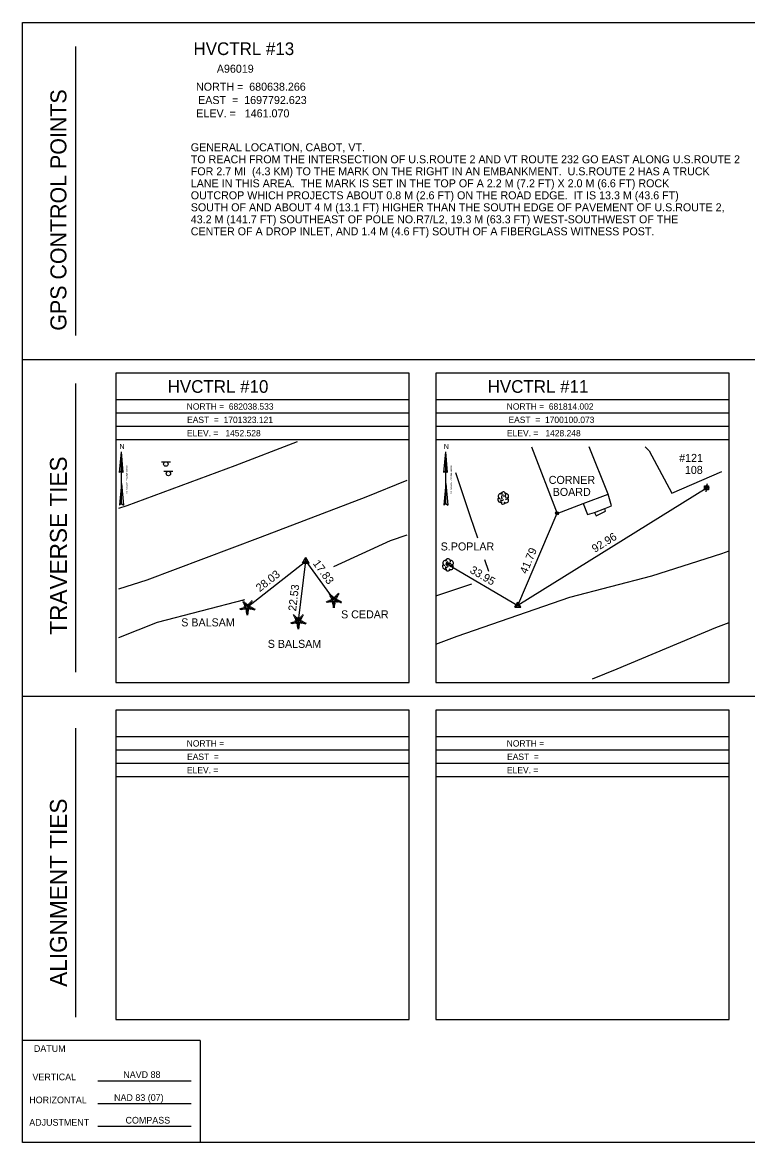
# Model space of a CAD drawing. Extents: x 1702290 to 1703620, y 686233 to 686653.
# Drawn here: x 1702980.5 to 1703252.4, y 686232.9 to 686652.9 of the extents above; entities that cross this region are included whole.
import ezdxf

# ---------------------------------------------------------------- set-up
doc = ezdxf.new("R2010")
doc.units = 0
for name, color, linetype in [('C_C', 7, 'Continuous'), ('CBP', 7, 'Continuous'), ('CPSM', 7, 'Continuous'), ('Default', 7, 'Continuous'), ('L_C', 7, 'Continuous'), ('LABL', 7, 'Continuous'), ('LAWA', 7, 'Continuous'), ('LBC', 7, 'Continuous'), ('LBF', 7, 'Continuous'), ('LTC', 7, 'Continuous'), ('LTD', 7, 'Continuous'), ('NBL1', 7, 'Continuous'), ('NBL2', 7, 'Continuous'), ('NNA_P', 7, 'Continuous'), ('PET', 7, 'Continuous'), ('SSGN', 7, 'Continuous'), ('U_C', 7, 'Continuous'), ('UP', 7, 'Continuous')]:
    doc.layers.add(name, color=color, linetype=linetype)

msp = doc.modelspace()

# ---------------------------------------------------------------- linework, layer by layer
at = {"layer": 'CBP'}
for centre, radius in [((1703237.33, 686478.43), 0.562), ((1703237.33, 686478.43), 0.075), ((1703181.02, 686468.85), 0.562), ((1703181.02, 686468.85), 0.075), ((1703139.95, 686449.77), 0.562), ((1703139.95, 686449.77), 0.075), ((1703097.25, 686436.43), 0.625), ((1703097.25, 686436.43), 0.0833), ((1703064.72, 686433.61), 0.625), ((1703064.72, 686433.61), 0.0833), ((1703084.06, 686428.51), 0.625), ((1703084.06, 686428.51), 0.0833)]:
    msp.add_circle(centre, radius, dxfattribs=at)
at = {"layer": 'CPSM'}
for p, q in [((1703085.55, 686450.16), (1703086.8, 686452.33)), ((1703088.05, 686450.16), (1703086.8, 686452.33)), ((1703086.8, 686450.88), (1703086.8, 686452.33)), ((1703085.55, 686450.16), (1703086.8, 686450.88)), ((1703085.55, 686450.16), (1703088.05, 686450.16)), ((1703086.8, 686450.88), (1703086.8, 686450.88)), ((1703086.8, 686450.88), (1703088.05, 686450.16)), ((1703165.14, 686433.6), (1703166.27, 686435.55)), ((1703167.39, 686433.6), (1703166.27, 686435.55)), ((1703166.27, 686434.25), (1703166.27, 686435.55)), ((1703165.14, 686433.6), (1703166.27, 686434.25)), ((1703165.14, 686433.6), (1703167.39, 686433.6)), ((1703166.27, 686434.25), (1703166.27, 686434.25)), ((1703166.27, 686434.25), (1703167.39, 686433.6))]:
    msp.add_line(p, q, dxfattribs=at)
at = {"layer": 'Default'}
for p, q in [((1703237.33, 686478.43), (1703166.27, 686434.25)), ((1703166.27, 686434.25), (1703181.02, 686468.85)), ((1703064.72, 686433.61), (1703086.8, 686450.88)), ((1703084.06, 686428.51), (1703086.8, 686450.88)), ((1703086.8, 686450.88), (1703097.25, 686436.43)), ((1703139.95, 686449.77), (1703166.27, 686434.25))]:
    msp.add_line(p, q, dxfattribs=at)
at = {"layer": 'LABL'}
for points in [[(1703151.22, 686459.51), (1703148.57, 686467.53), (1703143.01, 686483.97)], [(1703155.36, 686446.98), (1703153.91, 686451.39)], [(1703135.49, 686437.93), (1703148.99, 686442.39)]]:
    msp.add_lwpolyline(points, dxfattribs=at)
at = {"layer": 'LAWA'}
for points in [[(1703214.08, 686493.75), (1703215.47, 686492.29), (1703223.99, 686476.44), (1703242.82, 686484.48)], [(1703097.31, 686448.93), (1703118.5, 686458.68), (1703124.74, 686460.76)], [(1703016.69, 686422.33), (1703031.19, 686428.02), (1703063.96, 686436.53)]]:
    msp.add_lwpolyline(points, dxfattribs=at)
at = {"layer": 'LBC'}
msp.add_lwpolyline([(1703171.37, 686493.75), (1703180.98, 686468.78), (1703190.8, 686472.47), (1703200.1, 686476.07), (1703193.08, 686493.75)], dxfattribs=at)
at = {"layer": 'LBF'}
for points in [[(1703190.8, 686472.47), (1703192.35, 686468.33), (1703194.98, 686469.18), (1703198.87, 686470.66), (1703201.43, 686471.59), (1703200.1, 686476.07)], [(1703194.98, 686469.18), (1703195.61, 686467.89), (1703199.09, 686469.69), (1703198.87, 686470.66)]]:
    msp.add_lwpolyline(points, dxfattribs=at)
at = {"layer": 'LTC'}
for p, q in [((1703062.98, 686435.85), (1703063.33, 686436.11)), ((1703063.19, 686435.38), (1703063.72, 686435.77)), ((1703063.4, 686434.92), (1703064.1, 686435.43)), ((1703066, 686435.74), (1703066.55, 686435.34)), ((1703066.38, 686436.09), (1703066.79, 686435.78)), ((1703094.45, 686435.89), (1703094.6, 686435.42)), ((1703094.9, 686436.11), (1703095.11, 686435.46)), ((1703095.36, 686436.33), (1703095.63, 686435.49)), ((1703095.41, 686438.61), (1703095.77, 686438.87)), ((1703095.62, 686438.15), (1703096.15, 686438.53)), ((1703095.81, 686436.54), (1703096.14, 686435.52)), ((1703095.83, 686437.68), (1703096.54, 686438.19)), ((1703096.04, 686437.22), (1703096.92, 686437.85)), ((1703096.27, 686436.76), (1703097.28, 686437.5)), ((1703096.27, 686436.76), (1703096.66, 686435.57)), ((1703097.89, 686435.57), (1703096.66, 686435.57)), ((1703097.28, 686437.5), (1703098.28, 686436.77)), ((1703097.7, 686437.81), (1703098.51, 686437.22)), ((1703098.28, 686436.77), (1703097.89, 686435.57)), ((1703098.07, 686438.16), (1703098.75, 686437.66)), ((1703098.71, 686436.5), (1703098.38, 686435.46)), ((1703098.44, 686438.51), (1703098.99, 686438.11)), ((1703098.81, 686438.85), (1703099.23, 686438.55)), ((1703099.16, 686436.25), (1703098.87, 686435.37)), ((1703099.6, 686436), (1703099.37, 686435.27)), ((1703100.05, 686435.75), (1703099.86, 686435.18)), ((1703062.01, 686433.13), (1703062.16, 686432.66)), ((1703062.46, 686433.34), (1703062.68, 686432.69)), ((1703062.92, 686433.56), (1703063.19, 686432.72)), ((1703063.38, 686433.78), (1703063.71, 686432.76)), ((1703063.61, 686434.45), (1703064.48, 686435.09)), ((1703063.83, 686434), (1703064.84, 686434.73)), ((1703063.83, 686434), (1703064.22, 686432.8)), ((1703065.45, 686432.8), (1703064.22, 686432.8)), ((1703065.41, 686432.3), (1703064.26, 686432.3)), ((1703065.33, 686431.8), (1703064.34, 686431.8)), ((1703065.24, 686431.3), (1703064.41, 686431.3)), ((1703064.84, 686434.73), (1703065.84, 686434.01)), ((1703065.26, 686435.04), (1703066.07, 686434.45)), ((1703065.84, 686434.01), (1703065.45, 686432.8)), ((1703065.63, 686435.39), (1703066.31, 686434.9)), ((1703066.28, 686433.73), (1703065.94, 686432.69)), ((1703066.72, 686433.48), (1703066.43, 686432.6)), ((1703067.17, 686433.23), (1703066.93, 686432.5)), ((1703067.61, 686432.98), (1703067.42, 686432.41)), ((1703097.85, 686435.07), (1703096.7, 686435.07)), ((1703097.76, 686434.57), (1703096.78, 686434.57)), ((1703097.68, 686434.07), (1703096.85, 686434.07)), ((1703097.6, 686433.57), (1703096.92, 686433.57)), ((1703065.16, 686430.8), (1703064.48, 686430.8)), ((1703081.12, 686427.87), (1703081.28, 686427.41)), ((1703081.58, 686428.09), (1703081.79, 686427.44)), ((1703082.03, 686428.31), (1703082.31, 686427.47)), ((1703082.09, 686430.6), (1703082.45, 686430.85)), ((1703082.3, 686430.13), (1703082.83, 686430.51)), ((1703082.49, 686428.52), (1703082.82, 686427.51)), ((1703082.51, 686429.66), (1703083.21, 686430.18)), ((1703082.72, 686429.2), (1703083.6, 686429.84)), ((1703082.94, 686428.74), (1703083.96, 686429.48)), ((1703082.94, 686428.74), (1703083.33, 686427.55)), ((1703084.56, 686427.55), (1703083.33, 686427.55)), ((1703084.52, 686427.05), (1703083.38, 686427.05)), ((1703083.96, 686429.48), (1703084.95, 686428.75)), ((1703084.38, 686429.79), (1703085.19, 686429.2)), ((1703084.95, 686428.75), (1703084.56, 686427.55)), ((1703084.75, 686430.14), (1703085.43, 686429.65)), ((1703085.39, 686428.48), (1703085.05, 686427.44)), ((1703085.12, 686430.49), (1703085.67, 686430.09)), ((1703085.49, 686430.84), (1703085.91, 686430.53)), ((1703085.83, 686428.23), (1703085.55, 686427.35)), ((1703086.28, 686427.98), (1703086.04, 686427.25)), ((1703086.72, 686427.73), (1703086.54, 686427.16)), ((1703084.44, 686426.55), (1703083.45, 686426.55)), ((1703084.36, 686426.05), (1703083.52, 686426.05)), ((1703084.27, 686425.55), (1703083.6, 686425.55))]:
    msp.add_line(p, q, dxfattribs=at)
at = {"layer": 'LTD'}
for p, q in [((1703160.79, 686474.63), (1703160.79, 686474.63)), ((1703160.79, 686474.63), (1703160.79, 686474.63)), ((1703140.07, 686449.58), (1703140.07, 686449.58)), ((1703140.07, 686449.58), (1703140.07, 686449.58))]:
    msp.add_line(p, q, dxfattribs=at)
for centre in [(1703160.83, 686475.92), (1703140.11, 686450.87)]:
    msp.add_arc(centre, 0.942, 335.5272, 180.9563, dxfattribs=at)
for centre, major_axis, ratio, start_param, end_param in [((1703159.82, 686473.99), (0.525, -0.937), 0.959034, 3.141593, 6.283185), ((1703160.08, 686475.23), (1.09, -0.46), 0.895232, 1.570796, 4.712389), ((1703160.79, 686473.28), (0.238, 0.955), 0.942809, 1.570796, 4.712389), ((1703160.38, 686473.95), (-0.562, -0.075), 0.423636, 0, 3.141593), ((1703160.61, 686475.04), (-0.187, -0.713), 0.645439, 3.141593, 6.283185), ((1703161.24, 686474.48), (-0.45, 0.6), 0.989748, 3.141593, 6.283185), ((1703161.69, 686473.88), (-0.981, 0.713), 0.841452, 1.570796, 4.712389), ((1703161.73, 686475.15), (-1.03, -0.43), 0.949671, 1.570796, 4.712389), ((1703139.09, 686448.94), (0.525, -0.937), 0.959034, 3.141593, 6.283185), ((1703139.35, 686450.18), (1.09, -0.46), 0.895232, 1.570796, 4.712389), ((1703140.07, 686448.23), (0.238, 0.955), 0.942809, 1.570796, 4.712389), ((1703139.65, 686448.9), (-0.562, -0.075), 0.423636, 0, 3.141593), ((1703139.88, 686449.99), (-0.187, -0.713), 0.645439, 3.141593, 6.283185), ((1703140.52, 686449.43), (-0.45, 0.6), 0.989748, 3.141593, 6.283185), ((1703140.97, 686448.83), (-0.981, 0.713), 0.841452, 1.570796, 4.712389), ((1703141, 686450.1), (-1.03, -0.43), 0.949671, 1.570796, 4.712389)]:
    msp.add_ellipse(centre, major_axis=major_axis, ratio=ratio, start_param=start_param, end_param=end_param, dxfattribs=at)
at = {"layer": 'NBL1'}
for p, q in [((1703000.49, 686535.56), (1703000.49, 686643.9)), ((1702980.49, 686526.56), (1703620.49, 686526.56)), ((1703000.49, 686409.23), (1703000.49, 686517.56)), ((1702980.49, 686400.23), (1703620.49, 686400.23)), ((1703000.49, 686279.9), (1703000.49, 686388.23)), ((1703125.49, 686385.06), (1703015.49, 686385.06)), ((1703245.49, 686385.06), (1703135.49, 686385.06)), ((1703125.49, 686380.06), (1703015.49, 686380.06)), ((1703245.49, 686380.06), (1703135.49, 686380.06)), ((1703125.49, 686375.06), (1703015.49, 686375.06)), ((1703245.49, 686375.06), (1703135.49, 686375.06)), ((1703125.49, 686370.06), (1703015.49, 686370.06)), ((1703245.49, 686370.06), (1703135.49, 686370.06))]:
    msp.add_line(p, q, dxfattribs=at)
for points in [[(1703620.49, 686232.9), (1702980.49, 686232.9), (1702980.49, 686652.9), (1703620.49, 686652.9)], [(1703015.49, 686279.06), (1703125.49, 686279.06), (1703125.49, 686395.06), (1703015.49, 686395.06)], [(1703135.49, 686279.06), (1703245.49, 686279.06), (1703245.49, 686395.06), (1703135.49, 686395.06)]]:
    msp.add_lwpolyline(points, close=True, dxfattribs=at)
at = {"layer": 'NBL2'}
for p, q in [((1703125.49, 686511.38), (1703015.49, 686511.38)), ((1703245.49, 686511.38), (1703135.49, 686511.38)), ((1703125.49, 686506.38), (1703015.49, 686506.38)), ((1703245.49, 686506.38), (1703135.49, 686506.38)), ((1703125.49, 686501.38), (1703015.49, 686501.38)), ((1703245.49, 686501.38), (1703135.49, 686501.38)), ((1703125.49, 686496.38), (1703015.49, 686496.38)), ((1703245.49, 686496.38), (1703135.49, 686496.38)), ((1703047.16, 686271.15), (1702980.49, 686271.15)), ((1703047.16, 686271.15), (1703047.16, 686232.9)), ((1703047.16, 686271.15), (1703047.16, 686232.9)), ((1703008.73, 686256.09), (1703043.73, 686256.09)), ((1703008.73, 686247.5), (1703043.73, 686247.5)), ((1703008.73, 686239.06), (1703043.73, 686239.06))]:
    msp.add_line(p, q, dxfattribs=at)
for points in [[(1703015.49, 686405.38), (1703125.49, 686405.38), (1703125.49, 686521.38), (1703015.49, 686521.38)], [(1703135.49, 686405.38), (1703245.49, 686405.38), (1703245.49, 686521.38), (1703135.49, 686521.38)]]:
    msp.add_lwpolyline(points, close=True, dxfattribs=at)
at = {"layer": 'NNA_P'}
for p, q in [((1703016.95, 686484.1), (1703017.64, 686491.89)), ((1703017.64, 686472.52), (1703017.64, 686491.89)), ((1703018.34, 686484.1), (1703017.64, 686491.89)), ((1703138.56, 686484.1), (1703139.25, 686491.89)), ((1703139.26, 686472.52), (1703139.25, 686491.89)), ((1703139.95, 686484.1), (1703139.25, 686491.89)), ((1703016.95, 686484.1), (1703017.64, 686484.87)), ((1703018.34, 686484.1), (1703017.64, 686484.87)), ((1703138.56, 686484.1), (1703139.25, 686484.87)), ((1703139.95, 686484.1), (1703139.25, 686484.87)), ((1703017.65, 686480.04), (1703016.92, 686471.88)), ((1703017.64, 686480.04), (1703018.37, 686471.88)), ((1703139.26, 686480.04), (1703138.53, 686471.88)), ((1703139.25, 686480.04), (1703139.98, 686471.88)), ((1703017.65, 686472.52), (1703016.92, 686471.88)), ((1703017.65, 686472.52), (1703018.37, 686471.88)), ((1703139.26, 686472.52), (1703138.53, 686471.88)), ((1703139.26, 686472.52), (1703139.98, 686471.88))]:
    msp.add_line(p, q, dxfattribs=at)
at = {"layer": 'PET'}
for points in [[(1703016.69, 686470.73), (1703019.76, 686471.71), (1703060.34, 686486.76), (1703083.69, 686495.72)], [(1703016.69, 686440.57), (1703027.33, 686443.95), (1703069.78, 686459.93), (1703109.42, 686474.97), (1703124.74, 686481.21)], [(1703135.49, 686419.72), (1703143.53, 686422.78), (1703185.8, 686437.45), (1703216.52, 686445.44), (1703242.75, 686453.71), (1703245.49, 686454.82)], [(1703194.32, 686406.83), (1703203.48, 686410.51), (1703240.47, 686426.04), (1703245.49, 686427.9)]]:
    msp.add_lwpolyline(points, dxfattribs=at)
at = {"layer": 'SSGN'}
for p, q in [((1703032.64, 686488.15), (1703035.97, 686488.15)), ((1703034.28, 686487.31), (1703034.28, 686487.31)), ((1703033.59, 686484.58), (1703036.92, 686484.58)), ((1703035.24, 686483.75), (1703035.24, 686483.75))]:
    msp.add_line(p, q, dxfattribs=at)
for centre in [(1703034.28, 686487.31), (1703035.24, 686483.75)]:
    msp.add_circle(centre, 0.833, dxfattribs=at)
at = {"layer": 'UP'}
for p, q in [((1703236.32, 686477.58), (1703236.32, 686479.08)), ((1703236.32, 686479.08), (1703237.82, 686479.08)), ((1703237.82, 686477.58), (1703236.32, 686477.58)), ((1703236.84, 686476.83), (1703237.07, 686477.58)), ((1703237.29, 686479.83), (1703237.07, 686479.08)), ((1703237.07, 686478.33), (1703237.07, 686478.33)), ((1703237.82, 686479.08), (1703237.82, 686477.58))]:
    msp.add_line(p, q, dxfattribs=at)
msp.add_circle((1703237.07, 686478.33), 0.75, dxfattribs=at)

# ---------------------------------------------------------------- texts
at = {"layer": 'C_C'}
for s, p in [('CORNER', (1703177.87, 686479.86)), ('BOARD', (1703179.35, 686475.36))]:
    msp.add_text(s, height=3, dxfattribs=at).set_placement(p)
at = {"layer": 'Default'}
for s, p in [('GENERAL LOCATION, CABOT, VT.  ', (1703043.63, 686604.57)), ('TO REACH FROM THE INTERSECTION OF U.S.ROUTE 2 AND VT ROUTE 232 GO EAST ALONG U.S.ROUTE 2 ', (1703043.63, 686600.07)), ('FOR 2.7 MI  (4.3 KM) TO THE MARK ON THE RIGHT IN AN EMBANKMENT.  U.S.ROUTE 2 HAS A TRUCK ', (1703043.63, 686595.57)), ('LANE IN THIS AREA.  THE MARK IS SET IN THE TOP OF A 2.2 M (7.2 FT) X 2.0 M (6.6 FT) ROCK ', (1703043.63, 686591.07)), ('OUTCROP WHICH PROJECTS ABOUT 0.8 M (2.6 FT) ON THE ROAD EDGE.  IT IS 13.3 M (43.6 FT) ', (1703043.63, 686586.57)), ('SOUTH OF AND ABOUT 4 M (13.1 FT) HIGHER THAN THE SOUTH EDGE OF PAVEMENT OF U.S.ROUTE 2, ', (1703043.63, 686582.07)), ('43.2 M (141.7 FT) SOUTHEAST OF POLE NO.R7/L2, 19.3 M (63.3 FT) WEST-SOUTHWEST OF THE ', (1703043.63, 686577.57)), ('CENTER OF A DROP INLET, AND 1.4 M (4.6 FT) SOUTH OF A FIBERGLASS WITNESS POST. ', (1703043.63, 686573.07))]:
    msp.add_text(s, height=3, dxfattribs=at).set_placement(p)
for s, rotation, p in [('92.96', 31.8683, (1703195.17, 686453.98)), ('41.79', 66.9198, (1703169.6, 686445.88)), ('17.83', 305.8623, (1703089.26, 686450.04)), ('33.95', 329.4768, (1703148.02, 686446.75)), ('28.03', 38.0327, (1703069.49, 686439.24)), ('22.53', 83.0084, (1703083.11, 686432.03))]:
    msp.add_text(s, height=3, rotation=rotation, dxfattribs=at).set_placement(p)
at = {"layer": 'L_C'}
for s, p in [('S.POPLAR', (1703137.35, 686454.91)), ('S CEDAR', (1703099.99, 686429.46)), ('S BALSAM', (1703040.06, 686426.44)), ('S BALSAM', (1703072.49, 686418.39))]:
    msp.add_text(s, height=3, dxfattribs=at).set_placement(p)
at = {"layer": 'LTC'}
for p in [(1703097.16, 686436.51), (1703064.72, 686433.74), (1703083.84, 686428.49)]:
    msp.add_text('.', height=1.04, rotation=270, dxfattribs=at).set_placement(p)
at = {"layer": 'NBL1'}
for s, height, p in [('GPS CONTROL POINTS', 6, (1702996.99, 686537.31)), ('TRAVERSE TIES', 6.3332, (1702997.16, 686423.33)), ('ALIGNMENT TIES', 6.3332, (1702997.16, 686291.3))]:
    msp.add_text(s, height=height, rotation=90, dxfattribs=at).set_placement(p)
for s, p in [('NORTH =             ', (1703042.11, 686381.38)), ('NORTH =             ', (1703162.11, 686381.38)), ('EAST  =             ', (1703042.25, 686376.38)), ('EAST  =             ', (1703162.25, 686376.38)), ('ELEV. =             ', (1703042.22, 686371.38)), ('ELEV. =             ', (1703162.22, 686371.38))]:
    msp.add_text(s, height=2.375, dxfattribs=at).set_placement(p)
at = {"layer": 'NBL2'}
for s, height, p in [('     HVCTRL #13    ', 4.75, (1703035.83, 686640.66)), ('       A96019       ', 3, (1703045.6, 686634.03)), ('NORTH =  680638.266 ', 3, (1703045.6, 686627.29)), ('EAST  =  1697792.623', 3, (1703046.39, 686622.29)), ('ELEV. =   1461.070  ', 3, (1703045.7, 686617.29)), ('     HVCTRL #10    ', 4.75, (1703026.14, 686514.01)), ('     HVCTRL #11    ', 4.75, (1703146.14, 686514.01)), ('NORTH =  682038.533 ', 2.375, (1703042.11, 686507.7)), ('NORTH =  681814.002 ', 2.375, (1703162.11, 686507.7)), ('EAST  =  1701323.121', 2.375, (1703042.25, 686502.7)), ('EAST  =  1700100.073', 2.375, (1703162.77, 686502.7)), ('ELEV. =   1452.528  ', 2.375, (1703042.22, 686497.7)), ('ELEV. =   1428.248  ', 2.375, (1703162.22, 686497.7)), ('DATUM', 2.5, (1702984.81, 686266.91)), ('NAVD 88', 2.5, (1703018.33, 686257.14)), ('NAD 83 (07)', 2.5, (1703014.87, 686248.52)), ('HORIZONTAL', 2.5, (1702983.07, 686247.65)), ('COMPASS', 2.5, (1703019.17, 686240.04)), ('ADJUSTMENT', 2.5, (1702983.07, 686239.21))]:
    msp.add_text(s, height=height, dxfattribs=at).set_placement(p)
msp.add_text('VERTICAL', height=2.5, rotation=0.1439, dxfattribs=at).set_placement((1702984.27, 686256.24))
at = {"layer": 'NNA_P'}
for p in [(1703016.88, 686492.9), (1703138.49, 686492.9)]:
    msp.add_text('N', height=1.97, dxfattribs=at).set_placement(p)
for p in [(1703020, 686476.08), (1703141.61, 686476.08)]:
    msp.add_text('VT STATE PLANE GRID', height=0.7, rotation=90.0204, dxfattribs=at).set_placement(p)
at = {"layer": 'U_C'}
for s, p in [('#121', (1703226.78, 686488.11)), ('108', (1703228.92, 686483.61))]:
    msp.add_text(s, height=3, dxfattribs=at).set_placement(p)

doc.saveas('drawing.dxf')
